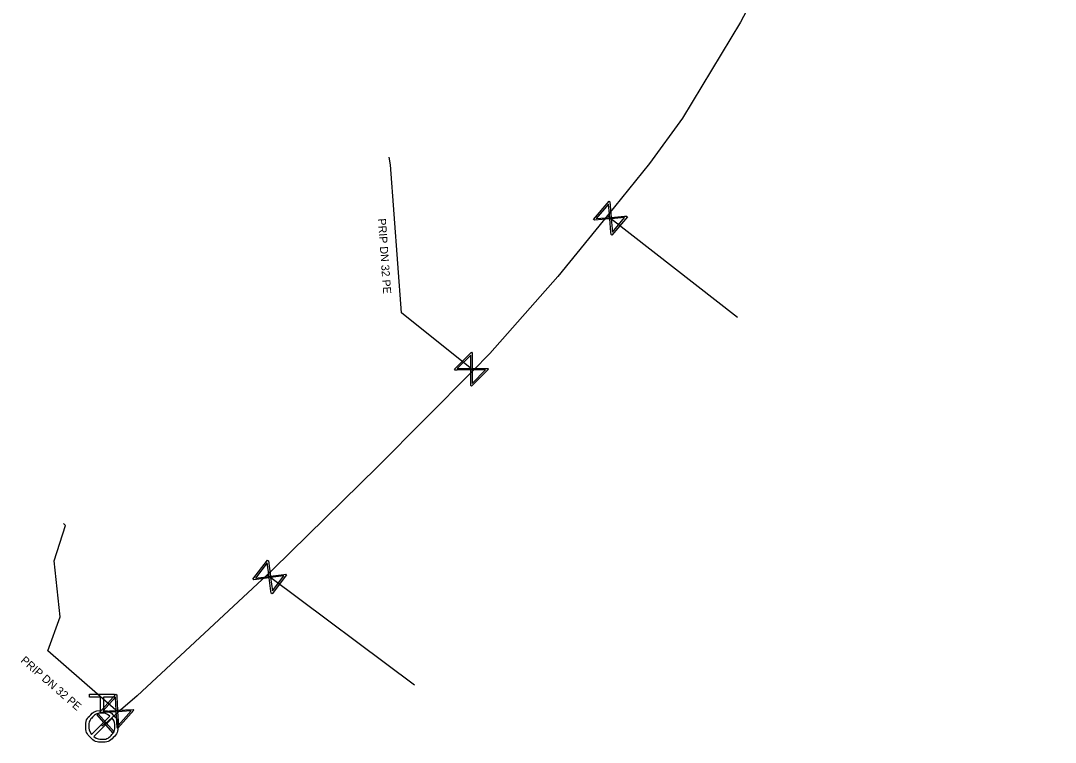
# Model space of a CAD drawing. Extents: x -643544 to -637295, y -1119190 to -1111715.
# Drawn here: x -642209.7 to -642145, y -1113975.6 to -1113930.5 of the extents above; entities that cross this region are included whole.
import ezdxf

# ---------------------------------------------------------------- set-up
doc = ezdxf.new("R2010")
doc.units = 0
for name, color, linetype in [('Default', 7, 'Continuous'), ('VP Hydrant', 7, 'Continuous'), ('VP Popis přípojky', 7, 'Continuous'), ('VP Přípojka', 7, 'Continuous'), ('VP Řad', 7, 'Continuous'), ('VP Šoupě', 7, 'Continuous')]:
    doc.layers.add(name, color=color, linetype=linetype)

msp = doc.modelspace()

# ---------------------------------------------------------------- linework, layer by layer
at = {"layer": 'Default'}
for points in [[(-642204.498, -1113973.594), (-642204.139, -1113973.623), (-642203.881, -1113973.883), (-642203.59, -1113974.176), (-642203.59, -1113974.592), (-642203.59, -1113975.006), (-642203.883, -1113975.298), (-642204.176, -1113975.59), (-642204.592, -1113975.59), (-642205.004, -1113975.59), (-642205.297, -1113975.298), (-642205.59, -1113975.006), (-642205.59, -1113974.592), (-642205.59, -1113974.176), (-642205.299, -1113973.883), (-642205.041, -1113973.621), (-642204.682, -1113973.594)], [(-642204.082, -1113973.953), (-642204.299, -1113973.776), (-642204.592, -1113973.776), (-642204.93, -1113973.776), (-642205.167, -1113974.013), (-642205.404, -1113974.25), (-642205.404, -1113974.588), (-642205.404, -1113974.881), (-642205.227, -1113975.098)], [(-642205.098, -1113975.227), (-642204.881, -1113975.401), (-642204.592, -1113975.401), (-642204.256, -1113975.401), (-642204.018, -1113975.163), (-642203.779, -1113974.926), (-642203.779, -1113974.588), (-642203.779, -1113974.299), (-642203.953, -1113974.082)]]:
    msp.add_open_spline(points, degree=3, dxfattribs=at)
at = {"layer": 'VP Hydrant'}
for points in [[(-642204.682, -1113973.594), (-642204.682, -1113972.774), (-642205.371, -1113972.774), (-642205.371, -1113972.59), (-642203.809, -1113972.59), (-642203.809, -1113972.774), (-642204.498, -1113972.774), (-642204.498, -1113973.594)], [(-642205.227, -1113975.098), (-642204.082, -1113973.953)], [(-642203.953, -1113974.082), (-642205.098, -1113975.227)]]:
    msp.add_lwpolyline(points, dxfattribs=at)
at = {"layer": 'VP Přípojka'}
for points in [[(-642181.417, -1113952.383), (-642181.587, -1113952.213), (-642185.88, -1113948.78), (-642186.55, -1113939.52), (-642186.64, -1113939.04)], [(-642173.013, -1113942.689), (-642172.817, -1113942.855), (-642164.89, -1113949.05)], [(-642203.577, -1113973.706), (-642203.724, -1113973.575), (-642207.96, -1113969.88), (-642207.19, -1113967.76), (-642207.57, -1113964.26), (-642206.86, -1113962.05), (-642206.98, -1113961.93)], [(-642194.263, -1113965.136), (-642194.045, -1113965.303), (-642185.06, -1113972)]]:
    msp.add_lwpolyline(points, dxfattribs=at)
at = {"layer": 'VP Řad'}
msp.add_lwpolyline([(-642145.25, -1113878.69), (-642145.03, -1113880.79), (-642147.82, -1113892.164), (-642149.184, -1113896.016), (-642152.24, -1113904.15), (-642154.4, -1113909.82), (-642156.95, -1113915.47), (-642158.708, -1113918.979), (-642161.785, -1113925.093), (-642164.69, -1113930.61), (-642166.505, -1113933.61), (-642168.32, -1113936.61), (-642170.37, -1113939.45), (-642173.013, -1113942.689), (-642176.11, -1113946.51), (-642180.35, -1113951.31), (-642181.417, -1113952.383), (-642187.38, -1113958.38), (-642193.88, -1113964.78), (-642194.263, -1113965.136), (-642202.38, -1113972.68), (-642203.577, -1113973.706), (-642204.36, -1113974.41), (-642204.59, -1113974.59)], dxfattribs=at)
at = {"layer": 'VP Šoupě'}
for points in [[(-642171.76, -1113942.769), (-642172.731, -1113943.912), (-642172.781, -1113943.87), (-642172.787, -1113943.741), (-642172.857, -1113942.904), (-642173.824, -1113942.984), (-642173.874, -1113942.942), (-642172.904, -1113941.798), (-642172.853, -1113941.841), (-642172.776, -1113942.809), (-642171.939, -1113942.74), (-642171.81, -1113942.726), (-642171.76, -1113942.769)], [(-642173.704, -1113942.886), (-642172.864, -1113942.817), (-642172.934, -1113941.978), (-642173.704, -1113942.886)], [(-642171.933, -1113942.828), (-642172.769, -1113942.897), (-642172.7, -1113943.731), (-642171.933, -1113942.828)], [(-642182.563, -1113952.298), (-642181.502, -1113951.237), (-642181.455, -1113951.284), (-642181.459, -1113951.413), (-642181.458, -1113952.253), (-642180.488, -1113952.252), (-642180.441, -1113952.298), (-642181.502, -1113953.359), (-642181.548, -1113953.312), (-642181.546, -1113952.341), (-642182.386, -1113952.342), (-642182.516, -1113952.345), (-642182.563, -1113952.298)], [(-642182.385, -1113952.253), (-642181.546, -1113952.253), (-642181.547, -1113951.416), (-642182.385, -1113952.253)], [(-642180.615, -1113952.34), (-642181.458, -1113952.341), (-642181.457, -1113953.182), (-642180.615, -1113952.34)], [(-642193.047, -1113965.124), (-642193.96, -1113966.314), (-642194.013, -1113966.274), (-642194.025, -1113966.146), (-642194.136, -1113965.313), (-642195.098, -1113965.441), (-642195.15, -1113965.4), (-642194.237, -1113964.211), (-642194.185, -1113964.251), (-642194.06, -1113965.214), (-642193.227, -1113965.104), (-642193.099, -1113965.084), (-642193.047, -1113965.124)], [(-642194.983, -1113965.337), (-642194.147, -1113965.226), (-642194.258, -1113964.392), (-642194.983, -1113965.337)], [(-642193.217, -1113965.192), (-642194.049, -1113965.302), (-642193.938, -1113966.131), (-642193.217, -1113965.192)], [(-642204.71, -1113973.702), (-642203.712, -1113972.582), (-642203.663, -1113972.625), (-642203.66, -1113972.754), (-642203.61, -1113973.592), (-642202.641, -1113973.535), (-642202.592, -1113973.579), (-642203.589, -1113974.699), (-642203.638, -1113974.655), (-642203.693, -1113973.685), (-642204.531, -1113973.735), (-642204.66, -1113973.746), (-642204.71, -1113973.702)], [(-642204.535, -1113973.647), (-642203.698, -1113973.597), (-642203.748, -1113972.762), (-642204.535, -1113973.647)], [(-642204.818, -1113973.814), (-642203.831, -1113974.944), (-642203.902, -1113975.006), (-642204.889, -1113973.876), (-642204.818, -1113973.814)], [(-642202.763, -1113973.63), (-642203.605, -1113973.68), (-642203.555, -1113974.52), (-642202.763, -1113973.63)]]:
    msp.add_lwpolyline(points, dxfattribs=at)

# ---------------------------------------------------------------- texts
at = {"layer": 'VP Popis přípojky'}
for rotation, p in [(274.13838, (-642187.35, -1113942.895)), (318.90094, (-642209.702, -1113970.541))]:
    msp.add_text('PRIP DN 32 PE', height=0.5, rotation=rotation, dxfattribs=at).set_placement(p)

doc.saveas('drawing.dxf')
